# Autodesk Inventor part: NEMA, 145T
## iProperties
Title: NEMA, 145T
Author: Administrator
Shininess: 21.0
PropertySet Name: _Private Model Information
Created: 2001-04
Part Number: MTR-00008-0
Material: Steel, Mild
Document SubType Name: Modeling
Designer: Administrator
Control State: 0
Master: False
Checked Out: False
PropertySet Name: Design Tracking Control
Density: 7.86
Volumn: 10701.284002384873
Area: 6819.382059126692
PropertySet Name: Model Information
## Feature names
1. Extrusion1
2. Chamfer1
3. Extrusion2
4. Extrusion3
5. Fillet1
6. Extrusion4
7. Fillet2
8. Revolution1
9. Extrusion5
10. Extrusion6
11. Extrusion7
12. Fillet3
13. Extrusion8
14. Fillet4
15. Keyway [Extrusion]
16. Circular Pattern1
